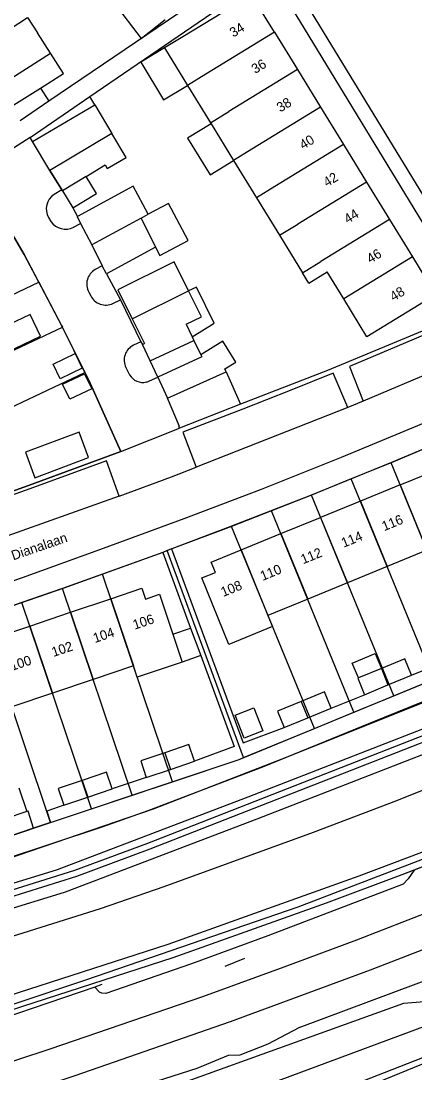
# Model space of a CAD drawing. Extents: x 194485 to 197793, y 468269 to 470822.
# Drawn here: x 195891.6 to 195940.6, y 469201.6 to 469332.6 of the extents above; entities that cross this region are included whole.
import ezdxf

# ---------------------------------------------------------------- set-up
doc = ezdxf.new("R2010")
doc.units = 0
for name, color, linetype in [('BGT begrenzing kruinlijn', 7, 'Continuous'), ('BGT grensvlak begroeid terreindeel', 7, 'Continuous'), ('BGT grensvlak begroeid terreindeel LR', 7, 'Continuous'), ('BGT grensvlak gebouwinstallatie plus 1', 7, 'Continuous'), ('BGT grensvlak onbegroeid terreindeel', 7, 'Continuous'), ('BGT grensvlak overig bouwwerk uitbreiding populatie', 7, 'Continuous'), ('BGT grensvlak pand op maaiveld', 7, 'Continuous'), ('BGT grensvlak pand op maaiveld LR', 7, 'Continuous'), ('BGT grensvlak waterdeel', 7, 'Continuous'), ('BGT grensvlak wegdeel', 7, 'Continuous'), ('BGT lijnelement scheiding geluidsscherm', 7, 'Continuous'), ('BGT lijnelement scheiding hek', 7, 'Continuous'), ('BGT lijnelement scheiding muur', 7, 'Continuous'), ('BGT lijnelement spoor trein', 7, 'Continuous'), ('BGT tekst huisnummerreeks', 7, 'Continuous'), ('BGT tekst openbare ruimte label weg', 7, 'Continuous'), ('GEM grensvlak WOZ_BRK percelen', 7, 'Continuous')]:
    doc.layers.add(name, color=color, linetype=linetype)

msp = doc.modelspace()

# ---------------------------------------------------------------- linework, layer by layer
at = {"layer": 'BGT begrenzing kruinlijn'}
for points in [[(196011.68, 469240.59), (196004.13, 469237.75), (195988.29, 469230.77), (195947.48, 469213.34), (195946.39, 469212.38), (195945.1, 469211.7), (195944.35, 469211.14), (195943.52, 469210.73), (195942.81, 469210.57), (195939.16, 469210.28), (195897.28, 469195.19), (195879.53, 469189.73), (195853.15, 469181.35), (195844.04, 469178.68), (195834.06, 469175.98)], [(195938.97, 469226.3), (195929.54, 469222.79), (195910.49, 469215.97), (195891.81, 469209.92), (195873.14, 469203.63), (195863.72, 469200.72), (195852.64, 469197.53), (195839.73, 469193.94)]]:
    msp.add_lwpolyline(points, dxfattribs=at)
at = {"layer": 'BGT grensvlak begroeid terreindeel'}
for points in [[(195977.75, 469262.45), (195947.27, 469250), (195924.8, 469240.98), (195908.05, 469234.49), (195891.2, 469228.72), (195874.46, 469223.35), (195854.32, 469217.11), (195847.58, 469215.25)], [(195806.02, 469201.64), (195814.19, 469203.4), (195857.05, 469214.94), (195896.14, 469226.97), (195919.84, 469236.03), (195946.27, 469246.32), (195975.87, 469258.98)], [(195977.05, 469256.22), (195947.4, 469243.54), (195920.92, 469233.23), (195897.11, 469224.13), (195857.89, 469212.06), (195814.9, 469200.48), (195807.51, 469198.89), (195807.31, 469198.85)], [(195835.93, 469168.56), (195850.59, 469172.63), (195876.12, 469179.94), (195889.94, 469184.48), (195902.05, 469188.58), (195907.49, 469190.51), (195924.09, 469196.72), (195944.24, 469204.6), (195963.93, 469212.5), (195986.7, 469222.13), (196011.58, 469233.49), (196012.58, 469233.54), (196013.02, 469233.37), (196013.69, 469232.61), (196014.11, 469231.67), (196014.15, 469230.9), (196013.89, 469230.29)], [(195829.74, 469193.2), (195839.26, 469195.68), (195850.77, 469198.88), (195861.89, 469202.08), (195871.04, 469204.86), (195876.71, 469206.71), (195891.29, 469211.67), (195909.92, 469217.66), (195933.68, 469226.18), (195943.64, 469229.96)]]:
    msp.add_lwpolyline(points, dxfattribs=at)
at = {"layer": 'BGT grensvlak begroeid terreindeel LR'}
msp.add_line((195940.49, 469226.89), (195938.97, 469226.3), dxfattribs=at)
for points in [[(195827.99, 469200.14), (195827.77, 469201.01), (195854.57, 469207.82), (195864.25, 469210.59), (195891.88, 469219.07), (195901.49, 469222.12), (195909.43, 469224.86), (195928, 469231.62), (195938.33, 469235.54), (195944.95, 469238.22), (195962.31, 469245.49), (195981.54, 469253.18)], [(196013.73, 469236.46), (196009.36, 469235.71), (195989.09, 469226.73), (195965.14, 469216.44), (195943.43, 469208.05), (195918.92, 469198.93), (195901.71, 469192.67), (195890.52, 469188.95), (195875.82, 469184.28), (195841.86, 469174.28), (195834.98, 469172.34)]]:
    msp.add_lwpolyline(points, dxfattribs=at)
at = {"layer": 'BGT grensvlak gebouwinstallatie plus 1'}
for p, q in [((195909.47, 469329.26), (195906.51, 469327.5)), ((195906.51, 469327.5), (195909.31, 469322.8)), ((195894.02, 469324.25), (195895.07, 469322.62)), ((195909.31, 469322.8), (195912.32, 469324.59)), ((195892.74, 469318.1), (195900.17, 469323.19)), ((195900.77, 469322.19), (195900.17, 469323.19)), ((195895.07, 469322.62), (195891.51, 469320.19)), ((195915.26, 469319.8), (195912.32, 469318.01)), ((195893.04, 469317.6), (195892.74, 469318.1)), ((195912.32, 469318.01), (195915.14, 469313.47)), ((195915.14, 469313.47), (195918.04, 469315.26)), ((195896.76, 469311.47), (195895.18, 469314.01)), ((195909.95, 469309.89), (195907.42, 469308.54)), ((195912.41, 469305.29), (195909.95, 469309.89)), ((195908.33, 469304.46), (195908.86, 469303.4)), ((195908.86, 469303.4), (195912.41, 469305.29)), ((195912.89, 469293.29), (195915.64, 469294.98)), ((195908.63, 469288.28), (195909.84, 469285.64)), ((195910.48, 469256.26), (195912.7, 469257.03)), ((195912.7, 469257.03), (195913.97, 469253.6)), ((195913.97, 469253.6), (195911.65, 469252.79)), ((195891.34, 469237.14), (195892.33, 469234.17))]:
    msp.add_line(p, q, dxfattribs=at)
for points in [[(195899.71, 469313.26), (195902.07, 469314.7), (195902.34, 469314.23), (195904.68, 469315.62), (195902.91, 469318.6)], [(195915.64, 469294.98), (195913.42, 469299.48), (195912.45, 469299.01)], [(195917.13, 469288.94), (195916.97, 469289.3), (195918.32, 469290.14), (195916.71, 469292.75), (195913.96, 469291.06)]]:
    msp.add_lwpolyline(points, dxfattribs=at)
at = {"layer": 'BGT grensvlak onbegroeid terreindeel'}
for p, q in [((195896.7, 469311.57), (195896.76, 469311.47)), ((195898.06, 469309.33), (195898.63, 469308.28)), ((195902.22, 469301.14), (195903.96, 469297.88)), ((195906.49, 469292.66), (195906.7, 469292.34))]:
    msp.add_line(p, q, dxfattribs=at)
msp.add_lwpolyline([(195895.29, 469232.82), (195893.18, 469232.11), (195887.18, 469230.1), (195885.17, 469229.43)], dxfattribs=at)
at = {"layer": 'BGT grensvlak overig bouwwerk uitbreiding populatie'}
for p, q in [((195932.8, 469252.67), (195935.66, 469253.85)), ((195935.66, 469253.85), (195936.43, 469251.98)), ((195933.58, 469250.81), (195932.8, 469252.67)), ((195918.23, 469246.18), (195920.55, 469247.1)), ((195920.55, 469247.1), (195921.69, 469244.23)), ((195919.37, 469243.3), (195918.23, 469246.18)), ((195921.69, 469244.23), (195919.37, 469243.3))]:
    msp.add_line(p, q, dxfattribs=at)
at = {"layer": 'BGT grensvlak pand op maaiveld'}
for p, q in [((195895.28, 469328.61), (195893.67, 469331.14)), ((195911.74, 469330.65), (195909.47, 469329.26)), ((195923.13, 469331.21), (195925.99, 469326.55)), ((195909.47, 469329.26), (195912.32, 469324.59)), ((195925.99, 469326.55), (195928.85, 469321.88)), ((195890.4, 469321.95), (195894.02, 469324.25)), ((195912.32, 469324.59), (195915.18, 469319.93)), ((195893.04, 469317.6), (195900.77, 469322.19)), ((195900.77, 469322.19), (195902.91, 469318.6)), ((195928.85, 469321.88), (195931.71, 469317.22)), ((195915.18, 469319.93), (195915.26, 469319.8)), ((195915.26, 469319.8), (195918.04, 469315.26)), ((195895.18, 469314.01), (195893.04, 469317.6)), ((195902.91, 469318.6), (195895.18, 469314.01)), ((195931.71, 469317.22), (195934.56, 469312.55)), ((195918.04, 469315.26), (195920.9, 469310.6)), ((195899.71, 469313.26), (195896.76, 469311.47)), ((195934.56, 469312.55), (195937.42, 469307.89)), ((195896.76, 469311.47), (195898.06, 469309.33)), ((195920.9, 469310.6), (195923.75, 469305.93)), ((195906.54, 469308.06), (195907.42, 469308.54)), ((195899.02, 469307.41), (195900.43, 469304.73)), ((195906.54, 469308.06), (195908.33, 469304.46)), ((195937.42, 469307.89), (195940.28, 469303.23)), ((195923.75, 469305.93), (195926.61, 469301.27)), ((195900.43, 469304.73), (195901.72, 469302.14)), ((195908.33, 469304.46), (195902.22, 469301.14)), ((195902.22, 469301.14), (195901.72, 469302.14)), ((195927.41, 469299.97), (195926.61, 469301.27)), ((195927.41, 469299.97), (195929.69, 469301.36)), ((195931.75, 469298), (195929.69, 469301.36)), ((195905.43, 469295.54), (195906.96, 469292.46)), ((195912.14, 469294.87), (195912.89, 469293.29)), ((195912.89, 469293.29), (195913.11, 469292.84)), ((195913.11, 469292.84), (195913.96, 469291.06)), ((195906.7, 469292.34), (195906.96, 469292.46)), ((195907.66, 469290.31), (195906.7, 469292.34)), ((195908.63, 469288.28), (195907.66, 469290.31)), ((195909.84, 469285.64), (195917.13, 469288.94)), ((195917.13, 469288.94), (195918.91, 469284.89)), ((195918.91, 469284.89), (195911.31, 469281.92)), ((195938.75, 469274.85), (195943.69, 469276.88)), ((195938.75, 469274.85), (195933.81, 469272.83)), ((195933.81, 469272.83), (195928.87, 469270.81)), ((195923.92, 469268.79), (195928.87, 469270.81)), ((195918.98, 469266.77), (195923.92, 469268.79)), ((195942.09, 469266.71), (195937.14, 469264.68)), ((195937.14, 469264.68), (195932.2, 469262.66)), ((195932.2, 469262.66), (195927.26, 469260.64)), ((195897.76, 469258.99), (195902.77, 469260.67)), ((195927.26, 469260.64), (195922.32, 469258.61)), ((195892.7, 469257.28), (195897.76, 469258.99)), ((195887.64, 469255.58), (195892.7, 469257.28)), ((195910.48, 469256.26), (195911.65, 469252.79)), ((195905.58, 469252.33), (195900.57, 469250.64)), ((195936.43, 469251.98), (195933.58, 469250.81)), ((195900.57, 469250.64), (195895.51, 469248.94)), ((195937.24, 469249.94), (195940.17, 469251.15)), ((195934.31, 469248.73), (195937.24, 469249.94)), ((195895.51, 469248.94), (195890.45, 469247.24)), ((195927.27, 469245.84), (195930.19, 469247.04)), ((195924.35, 469244.65), (195927.27, 469245.84)), ((195910.18, 469239.43), (195913.18, 469240.44)), ((195907.19, 469238.41), (195910.18, 469239.43)), ((195899.93, 469235.98), (195902.93, 469236.99)), ((195896.94, 469234.97), (195899.93, 469235.98)), ((195892.33, 469234.17), (195889.62, 469233.26))]:
    msp.add_line(p, q, dxfattribs=at)
for points in [[(195923.13, 469331.21), (195920.27, 469335.87), (195911.74, 469330.65)], [(195904.03, 469335.46), (195903.2, 469334.81), (195906.57, 469330.45), (195909.52, 469332.78)], [(195886.01, 469328.91), (195892.42, 469333.06), (195893.67, 469331.14)], [(195894.02, 469324.25), (195896.89, 469326.07), (195895.28, 469328.61)], [(195898.06, 469309.33), (195901.01, 469311.12), (195899.71, 469313.26)], [(195907.42, 469308.54), (195905.57, 469312.05), (195898.63, 469308.28)], [(195898.63, 469308.28), (195898.58, 469308.25), (195899.02, 469307.41)], [(195940.28, 469303.23), (195943.16, 469298.53), (195934.63, 469293.3), (195931.75, 469298)], [(195912.45, 469299.01), (195910.67, 469302.61), (195903.65, 469299.15), (195905.43, 469295.54)], [(195912.14, 469294.87), (195914.05, 469295.78), (195912.45, 469299.01)], [(195887.75, 469290.37), (195894.02, 469293.35), (195892.74, 469296.06), (195886.46, 469293.08), (195887.75, 469290.37)], [(195899.22, 469289.38), (195896.47, 469288.06), (195895.59, 469289.89), (195898.34, 469291.21), (195899.22, 469289.38)], [(195913.96, 469291.06), (195914.08, 469290.81), (195908.63, 469288.28)], [(195896.78, 469287.39), (195899.52, 469288.68), (195900.41, 469286.81), (195897.67, 469285.51), (195896.78, 469287.39)], [(195911.31, 469281.92), (195911.24, 469282.11), (195911.31, 469282.14), (195909.84, 469285.64)], [(195892.15, 469278.91), (195893.34, 469275.74), (195900.02, 469278.25), (195898.83, 469281.41), (195892.15, 469278.91)], [(195922.32, 469258.61), (195922.89, 469257.23), (195917.45, 469255), (195914.08, 469263.26), (195915.79, 469263.96), (195915.26, 469265.25), (195918.98, 469266.77)], [(195902.77, 469260.67), (195906.63, 469261.98), (195907.08, 469260.64), (195908.82, 469261.23), (195910.48, 469256.26)], [(195911.65, 469252.79), (195906.05, 469250.91), (195905.58, 469252.33)], [(195940.17, 469251.15), (195939.35, 469253.19), (195936.43, 469251.98)], [(195933.58, 469250.81), (195933.5, 469250.78), (195934.31, 469248.73)], [(195930.19, 469247.04), (195929.37, 469249.08), (195926.45, 469247.88)], [(195926.45, 469247.88), (195923.52, 469246.69), (195924.35, 469244.65)], [(195909.48, 469241.51), (195906.49, 469240.5), (195907.19, 469238.41)], [(195913.18, 469240.44), (195912.47, 469242.52), (195909.48, 469241.51)], [(195902.93, 469236.99), (195902.23, 469239.07), (195899.23, 469238.06)], [(195899.23, 469238.06), (195896.23, 469237.05), (195896.94, 469234.97)], [(195890.18, 469231.12), (195893.18, 469232.13), (195892.48, 469234.21), (195892.33, 469234.17)]]:
    msp.add_lwpolyline(points, dxfattribs=at)
at = {"layer": 'BGT grensvlak pand op maaiveld LR'}
for p, q in [((195923.13, 469331.21), (195914.6, 469325.99)), ((195888.79, 469324.48), (195895.28, 469328.61)), ((195914.6, 469325.99), (195912.32, 469324.59)), ((195925.99, 469326.55), (195917.46, 469321.32)), ((195928.85, 469321.88), (195920.32, 469316.66)), ((195915.18, 469319.93), (195917.46, 469321.32)), ((195920.32, 469316.66), (195918.04, 469315.26)), ((195931.71, 469317.22), (195923.18, 469312)), ((195934.56, 469312.55), (195926.03, 469307.33)), ((195923.18, 469312), (195920.9, 469310.6)), ((195906.54, 469308.06), (195900.43, 469304.73)), ((195923.75, 469305.93), (195926.03, 469307.33)), ((195937.42, 469307.89), (195928.89, 469302.67)), ((195940.28, 469303.23), (195931.75, 469298)), ((195926.61, 469301.27), (195928.89, 469302.67)), ((195905.43, 469295.54), (195912.45, 469299.01)), ((195907.66, 469290.31), (195913.11, 469292.84)), ((195938.75, 469274.85), (195942.09, 469266.71)), ((195933.81, 469272.83), (195937.14, 469264.68)), ((195928.87, 469270.81), (195932.2, 469262.66)), ((195923.92, 469268.79), (195927.26, 469260.64)), ((195918.98, 469266.77), (195922.32, 469258.61)), ((195902.77, 469260.67), (195905.58, 469252.33)), ((195897.76, 469258.99), (195900.57, 469250.64)), ((195892.7, 469257.28), (195895.51, 469248.94)), ((195936.43, 469251.98), (195937.24, 469249.94)), ((195926.45, 469247.88), (195927.27, 469245.84)), ((195909.48, 469241.51), (195910.18, 469239.43)), ((195899.23, 469238.06), (195899.93, 469235.98))]:
    msp.add_line(p, q, dxfattribs=at)
at = {"layer": 'BGT grensvlak waterdeel'}
for points in [[(195806.96, 469200.83), (195815.58, 469202.88), (195845.18, 469210.42), (195868.68, 469217.58), (195898.29, 469226.88), (195907.39, 469230.25), (195962.16, 469251.71), (195975.94, 469257.84)], [(195807.14, 469200.07), (195815.77, 469202.13), (195845.39, 469209.68), (195868.91, 469216.84), (195898.54, 469226.15), (195907.67, 469229.53), (195962.46, 469251), (195976.25, 469257.14)], [(196010.71, 469232.72), (195970.53, 469214.58), (195929.37, 469197.77), (195895.42, 469185.55), (195869.04, 469177.09), (195839.77, 469168.98), (195826.39, 469165.62)]]:
    msp.add_lwpolyline(points, dxfattribs=at)
at = {"layer": 'BGT grensvlak wegdeel'}
for p, q in [((195892.74, 469318.1), (195890.2, 469316.47)), ((195895.18, 469314.01), (195896.7, 469311.57)), ((195896.7, 469311.57), (195895.71, 469311.01)), ((195895.03, 469308.15), (195895.31, 469307.66)), ((195898.15, 469306.95), (195899.02, 469307.41)), ((195901.72, 469302.14), (195900.85, 469301.67)), ((195900.05, 469298.85), (195900.27, 469298.41)), ((195903.04, 469297.45), (195903.96, 469297.88)), ((195903.96, 469297.88), (195906.49, 469292.66)), ((195906.49, 469292.66), (195905.59, 469292.24)), ((195949.7, 469291.85), (195934.17, 469285.27)), ((195904.66, 469289.48), (195905.12, 469288.57)), ((195907.2, 469287.66), (195908.63, 469288.28)), ((195908.63, 469288.28), (195909.84, 469285.64)), ((195934.17, 469285.27), (195932.27, 469284.49)), ((195932.27, 469284.49), (195913.4, 469277.05)), ((195904.02, 469278.99), (195911.31, 469281.92)), ((195903.83, 469273.45), (195880.29, 469265.1)), ((195910.34, 469266.89), (195909.23, 469266.45)), ((195909.23, 469266.45), (195912.7, 469257.03)), ((195930.19, 469247.04), (195934.31, 469248.73)), ((195907.19, 469238.41), (195902.93, 469236.99)), ((195946.83, 469229.36), (195940.49, 469226.89))]:
    msp.add_line(p, q, dxfattribs=at)
for points in [[(195892.86, 469375.4), (195894.03, 469374.26), (195920.73, 469340.06), (195895.07, 469322.62)], [(195938.11, 469349.34), (195923.65, 469339.31), (195926.78, 469335.24), (195949.81, 469297.46)], [(195900.17, 469323.19), (195922.13, 469338.27), (195925.21, 469334.34), (195948.1, 469296.71)], [(195886.49, 469312.91), (195891.98, 469303.54), (195896.66, 469294.7), (195900.19, 469287.53), (195904.02, 469278.99)], [(195948.1, 469296.71), (195929.73, 469289.09), (195918.91, 469284.89)], [(195949.7, 469291.85), (195947.83, 469296.11), (195939.44, 469292.52), (195932.47, 469289.59), (195934.17, 469285.27)], [(195965.08, 469289.54), (195957.49, 469286.12), (195947.56, 469281.81), (195937.69, 469277.62), (195927.63, 469273.55), (195917.59, 469269.61), (195910.37, 469266.9), (195910.34, 469266.89)], [(195932.27, 469284.49), (195930.42, 469288.76), (195925.1, 469286.6), (195919.2, 469284.26), (195911.75, 469281.43), (195913.4, 469277.05)], [(195881.05, 469259.63), (195891.8, 469263.34), (195901.87, 469266.96), (195911.89, 469270.66), (195921.51, 469274.33), (195931.46, 469278.3), (195940.95, 469282.24), (195949.52, 469285.92), (195951.86, 469286.95)], [(195904.02, 469278.99), (195892.55, 469274.77), (195885.32, 469272.19), (195878.7, 469269.94), (195875.37, 469268.78)], [(195903.83, 469273.45), (195902.24, 469277.83), (195892.72, 469274.35), (195885.46, 469271.78), (195878.83, 469269.54), (195880.29, 469265.1)], [(195903.83, 469273.45), (195910.32, 469275.85), (195913.4, 469277.05)], [(195909.23, 469266.45), (195896.92, 469261.99), (195881.57, 469256.68), (195871.3, 469253.28), (195853.6, 469247.69)], [(195910.34, 469266.89), (195919.25, 469242.73), (195924.35, 469244.65)], [(195913.97, 469253.6), (195918.13, 469242.3), (195913.18, 469240.44)], [(195940.17, 469251.15), (195942.33, 469252.02), (195942.9, 469250.62)], [(195895.29, 469232.82), (195918.73, 469240.68), (195941.38, 469250), (195942.9, 469250.62)], [(195896.94, 469234.97), (195894.81, 469234.25), (195895.29, 469232.82)], [(195940.49, 469226.89), (195939.76, 469225.79), (195939.14, 469225.15), (195922.3, 469218.69), (195912.79, 469215.24), (195902.15, 469211.54), (195901.65, 469211.57), (195901.38, 469211.7), (195900.79, 469212.33), (195883.44, 469206.42), (195883.11, 469205.48), (195882.66, 469205.15), (195872.08, 469201.65), (195864.5, 469199.39), (195835.81, 469191.24), (195834.62, 469191.38), (195834.27, 469191.56), (195834.03, 469191.79), (195830.33, 469190.82)], [(195943.81, 469213.84), (195926.15, 469207.25), (195922.3, 469205.23), (195918.81, 469203.83), (195917.37, 469203.79), (195913.48, 469202.21), (195896.1, 469196.64), (195893.12, 469195.06), (195890.35, 469194.08), (195887.58, 469193.83), (195881.52, 469192.05), (195870.11, 469188.34), (195848.76, 469182.23), (195845.99, 469180.87), (195836.16, 469178.3), (195833.7, 469177.42)]]:
    msp.add_lwpolyline(points, dxfattribs=at)
for centre, radius, start, end in [((195896.88, 469309.22), 2.14, 123.0879, 210.0946), ((195897.13, 469308.88), 2.19, 213.9064, 297.9548), ((195901.85, 469299.86), 2.07, 119.0878, 209.2958), ((195902.13, 469299.3), 2.06, 205.7935, 296.1335), ((195906.48, 469290.4), 2.04, 115.9282, 206.8408), ((195906.75, 469289.48), 1.87, 209.1644, 283.7477)]:
    msp.add_arc(centre, radius, start, end, dxfattribs=at)
at = {"layer": 'BGT lijnelement scheiding geluidsscherm'}
msp.add_lwpolyline([(195829.99, 469192.2), (195844.97, 469196.2), (195858.9, 469200.14), (195873.25, 469204.38), (195899.68, 469213.23), (195926.07, 469222.33), (195954.84, 469233.35), (195975.33, 469242.23), (195999.72, 469253.21), (196015.74, 469260.89), (196023.82, 469265.15)], dxfattribs=at)
at = {"layer": 'BGT lijnelement scheiding hek'}
msp.add_line((195916.99, 469214.95), (195919.44, 469215.94), dxfattribs=at)
msp.add_lwpolyline([(195779.93, 469198.12), (195805.14, 469204.14), (195808.22, 469204.93), (195822.81, 469208.51), (195829.7, 469210.4), (195837.95, 469212.66), (195847.79, 469215.3), (195865.03, 469220.38), (195873.26, 469222.95), (195882.72, 469225.94), (195889.07, 469228.07), (195901.71, 469232.26), (195907.42, 469234.32), (195921.68, 469239.76), (195935.09, 469245.24), (195943.36, 469248.59)], dxfattribs=at)
at = {"layer": 'BGT lijnelement scheiding muur'}
msp.add_line((195948.28, 469229.92), (195938.97, 469226.3), dxfattribs=at)
msp.add_lwpolyline([(195901.66, 469212.63), (195900.79, 469212.33), (195883.44, 469206.42), (195882.33, 469206.04)], dxfattribs=at)
at = {"layer": 'BGT lijnelement spoor trein'}
for points in [[(195831.59, 469185.8), (195837.36, 469187.3), (195853.27, 469191.7), (195861.18, 469193.98), (195878.34, 469199.18), (195887.16, 469201.99), (195895.23, 469204.63), (195914.21, 469211.17), (195924.34, 469214.84), (195933.37, 469218.21), (195942.93, 469221.95), (195953.55, 469226.16), (195971.75, 469233.76), (195989.64, 469241.67), (195998.23, 469245.62), (196007.36, 469249.9), (196026.34, 469259.12), (196034.36, 469263.12)], [(195832.59, 469181.84), (195838.96, 469183.48), (195856.59, 469188.36), (195868, 469191.69), (195885.85, 469197.22), (195898.36, 469201.32), (195917.66, 469208.03), (195935.09, 469214.46), (195944.28, 469218.03), (195963.6, 469225.9), (195973.98, 469230.3), (195992.73, 469238.64), (196012.7, 469247.97), (196022.89, 469252.93), (196036.13, 469259.51)]]:
    msp.add_lwpolyline(points, dxfattribs=at)
at = {"layer": 'GEM grensvlak WOZ_BRK percelen'}
for p, q in [((195867.25, 469287.46), (195893.81, 469300.08)), ((195869.81, 469281.75), (195896.76, 469294.51)), ((195899.55, 469288.84), (195896.76, 469294.51)), ((195872.33, 469275.96), (195899.55, 469288.84)), ((195942.55, 469279.68), (195937.63, 469277.6)), ((195937.63, 469277.6), (195932.68, 469275.6)), ((195947.84, 469252.64), (195937.63, 469277.6)), ((195932.68, 469275.6), (195927.73, 469273.59)), ((195942.9, 469250.61), (195932.68, 469275.6)), ((195927.73, 469273.59), (195922.76, 469271.64)), ((195937.96, 469248.58), (195927.73, 469273.59)), ((195922.76, 469271.64), (195917.79, 469269.69)), ((195933.02, 469246.55), (195922.76, 469271.64)), ((195928.09, 469244.52), (195917.79, 469269.69)), ((195919.28, 469240.91), (195909.8, 469266.67)), ((195901.74, 469263.74), (195896.77, 469261.94)), ((195910.43, 469237.9), (195901.74, 469263.74)), ((195896.77, 469261.94), (195891.72, 469260.19)), ((195905.42, 469236.22), (195896.77, 469261.94)), ((195891.72, 469260.19), (195886.68, 469258.45)), ((195900.36, 469234.52), (195891.72, 469260.19)), ((195895.29, 469232.82), (195886.68, 469258.45)), ((195937.96, 469248.58), (195942.9, 469250.61)), ((195933.02, 469246.55), (195937.96, 469248.58)), ((195928.09, 469244.52), (195933.02, 469246.55)), ((195919.28, 469240.91), (195928.09, 469244.52)), ((195905.42, 469236.22), (195910.43, 469237.9)), ((195900.36, 469234.52), (195905.42, 469236.22)), ((195895.29, 469232.82), (195900.36, 469234.52)), ((195890.23, 469231.12), (195895.29, 469232.82))]:
    msp.add_line(p, q, dxfattribs=at)
for points in [[(195893.81, 469300.08), (195891.98, 469303.54), (195890.78, 469305.6)], [(195893.81, 469300.08), (195896.66, 469294.7), (195896.76, 469294.51)], [(195872.33, 469275.96), (195875.37, 469268.78), (195878.61, 469269.92), (195885.32, 469272.19), (195892.55, 469274.77), (195904.02, 469278.99), (195900.19, 469287.53), (195899.55, 469288.84)], [(195917.79, 469269.69), (195910.37, 469266.9), (195909.8, 469266.67)], [(195909.8, 469266.67), (195909.23, 469266.45), (195901.74, 469263.74)], [(195910.43, 469237.9), (195918.73, 469240.68), (195919.28, 469240.91)]]:
    msp.add_lwpolyline(points, dxfattribs=at)

# ---------------------------------------------------------------- texts
at = {"layer": 'BGT tekst huisnummerreeks'}
for s, rotation, p in [('34', 31.5, (195918.01, 469330.53)), ('36', 31.5, (195920.73, 469326)), ('38', 31.5, (195923.86, 469321.21)), ('40', 31.5, (195926.7, 469316.56)), ('42', 31.5, (195929.65, 469311.9)), ('44', 31.5, (195932.23, 469307.33)), ('46', 31.5, (195935.06, 469302.38)), ('48', 31.5, (195937.94, 469297.67)), ('116', 22.2, (195936.77, 469269.08)), ('114', 22.2, (195931.73, 469267.02)), ('112', 22.2, (195926.69, 469264.96)), ('110', 22.2, (195921.65, 469262.89)), ('108', 22.2, (195916.75, 469260.89)), ('106', 18.6, (195905.74, 469256.82)), ('104', 18.6, (195900.8, 469255.16)), ('102', 18.6, (195895.64, 469253.42)), ('100', 18.6, (195890.48, 469251.68))]:
    msp.add_text(s, height=1.2, rotation=rotation, dxfattribs=at).set_placement(p)
at = {"layer": 'BGT tekst openbare ruimte label weg'}
msp.add_text('Dianalaan', height=1.2, rotation=19, dxfattribs=at).set_placement((195890.65, 469265.45))

doc.saveas('drawing.dxf')
